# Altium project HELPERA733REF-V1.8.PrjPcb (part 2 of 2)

## Sheet 02 Power.SchDoc
size 386 x 246 mm
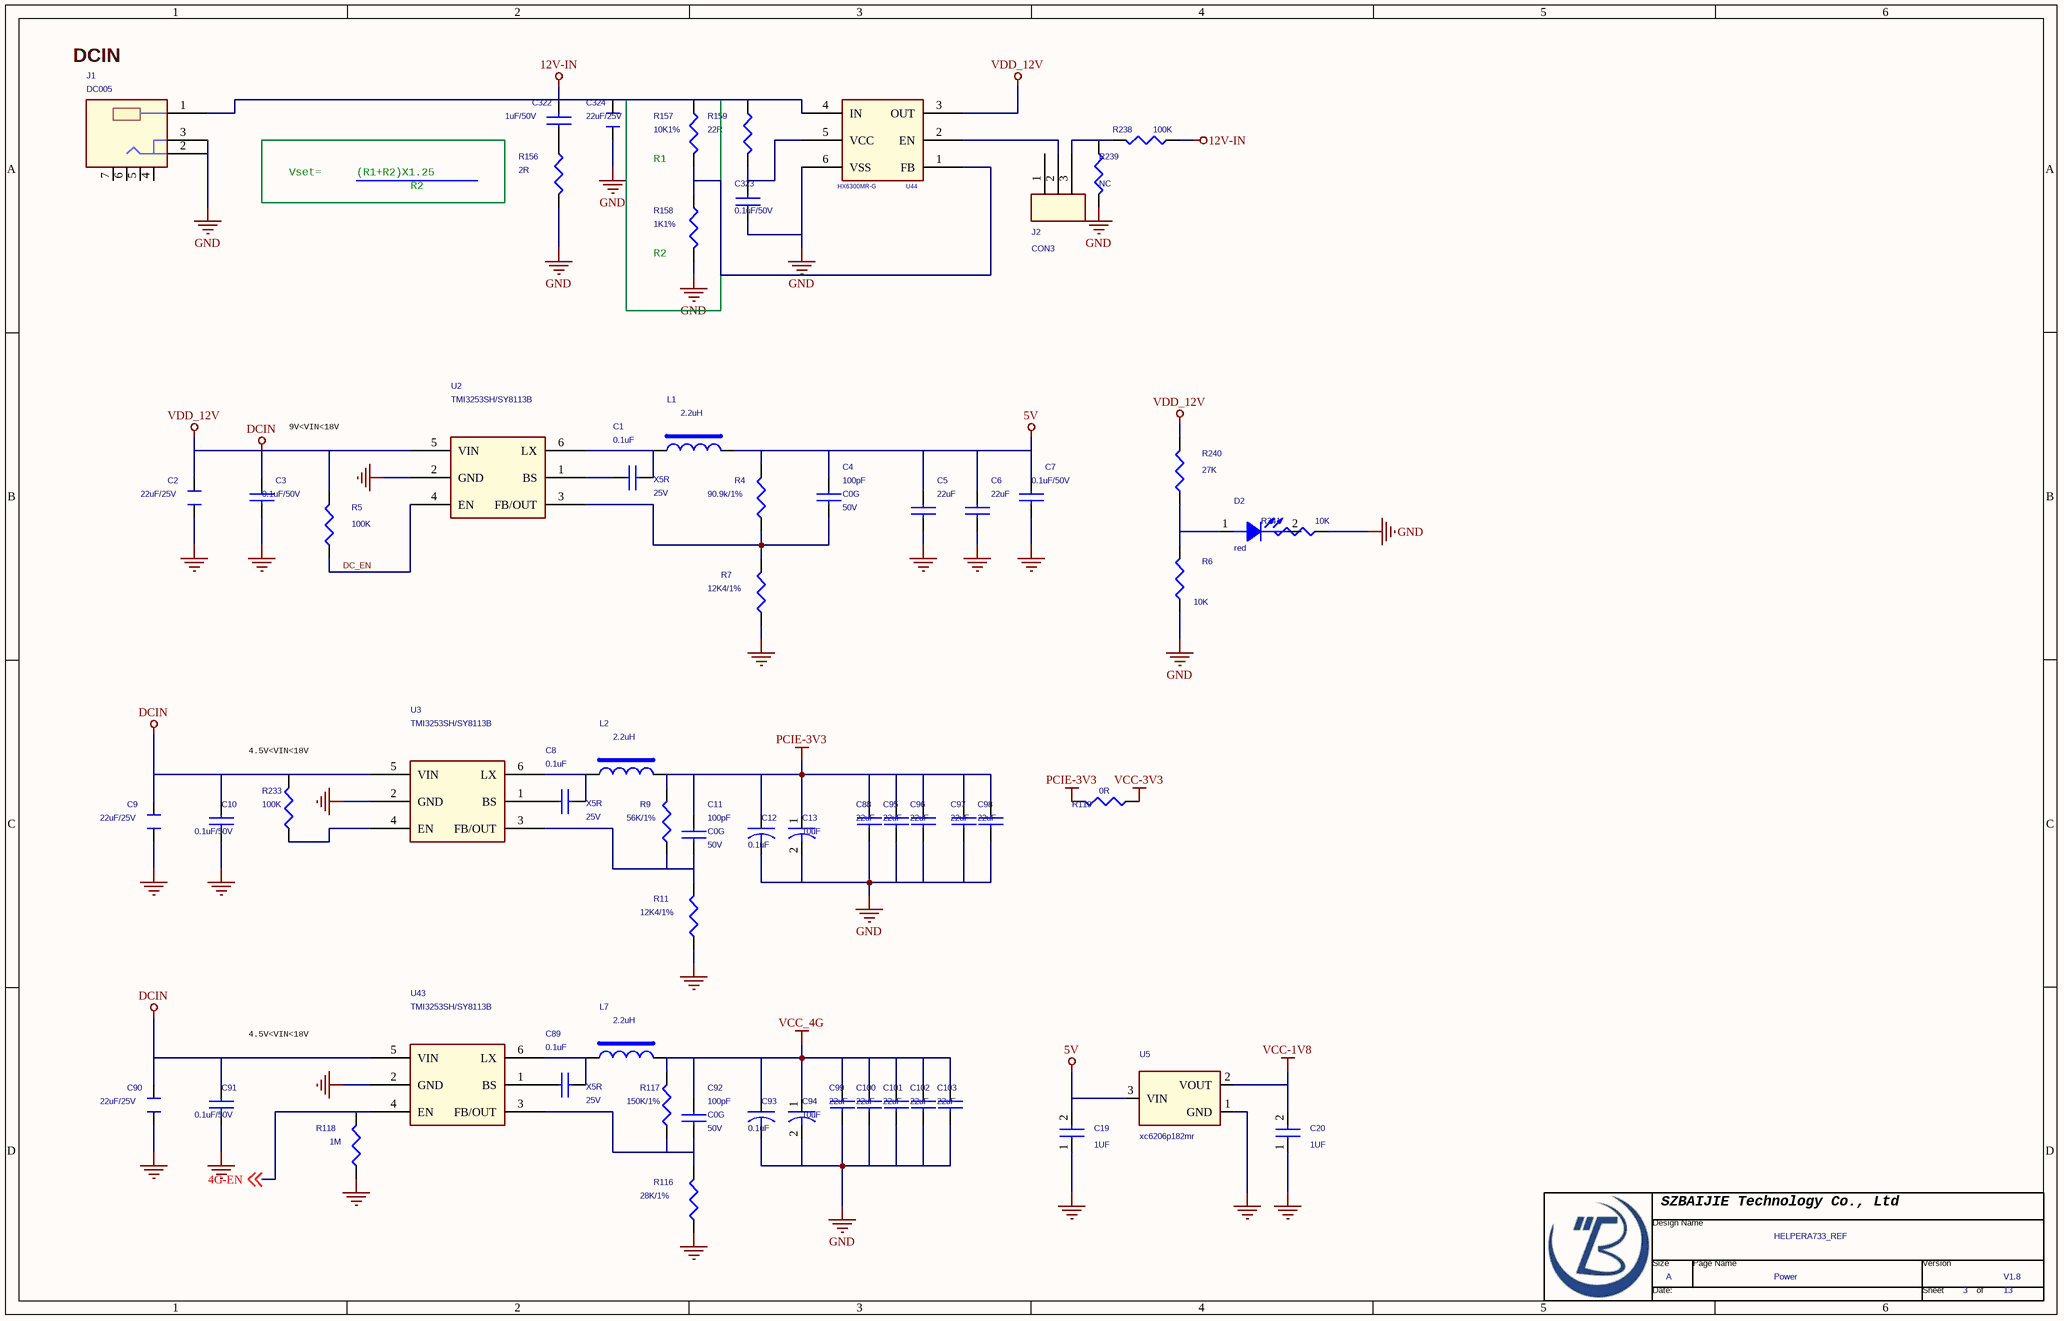
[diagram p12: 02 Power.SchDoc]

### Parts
(Parts that share a designator on the sheet are numbered #1, #2 ... from top to bottom, then left to right.)
*#11  Page Count: 13  Page Number: 3  Page Size: A  Title: HELPERA733_REF  RevCode: V1.8  Doc: Power  (hidden comment: TitleBlock0-BJ)  (graphical)
C1  0.1uF  Voltage: 25V  Dielectric: X5R  [C0402]
C2  22uF/25V  [C0805]
C3  0.1uF/50V  [C0402]
C4  100pF  Voltage: 50V  Dielectric: C0G  [C0402]
C5  22uF  [C0805]
C6  22uF  [C0805]
C7  0.1uF/50V  [C0402]
C8  0.1uF  Voltage: 25V  Dielectric: X5R  [C0402]
C9  22uF/25V  [C0805]
C10  0.1uF/50V  [C0402]
C11  100pF  Voltage: 50V  Dielectric: C0G  [C0402]
C12  0.1uF  [C0402]
C13  10uF  [C0603]
C19  1UF  [C0402]
C20  1UF  [C0402]
C88  22uF  [C0805]
C89  0.1uF  Voltage: 25V  Dielectric: X5R  [C0402]
C90  22uF/25V  [C0805]
C91  0.1uF/50V  [C0402]
C92  100pF  Voltage: 50V  Dielectric: C0G  [C0402]
C93  0.1uF  [C0402]
C94  10uF  [C0603]
C95  22uF  [C0805]
C96  22uF  [C0805]
C97  22uF  [C0805]
C98  22uF  [C0805]
C99  22uF  [C0805]
C100  22uF  [C0805]
C101  22uF  [C0805]
C102  22uF  [C0805]
C103  22uF  [C0805]
C322  1uF/50V  [C0603]
C323  0.1uF/50V  [C0402]
C324  22uF/25V  [C0805]
D2  red  [D0603]
J1  DC005  [TSH-3865D]
J2  CON3  [SS-12F44(1P2T)]
L1  2.2uH  [4018]
L2  2.2uH  [4018]
L7  2.2uH  [4018]
R4  90.9k/1%  [R0402]
R5  100K  [R0402]
R6  10K  [R0402]
R7  12K4/1%  [R0402]
R9  56K/1%  [R0402]
R11  12K4/1%  [R0402]
R116  28K/1%  [R0402]
R117  150K/1%  [R0402]
R118  1M  [R0402]
R119  0R  [R0805]
R156  2R  [R0603]
R157  10K1%  [R0402]
R158  1K1%  [R0402]
R159  22R  [R0402]
R233  100K  [R0402]
R238  100K  [R0402]
R239  NC  [R0402]
R240  27K  [R0402]
R241  10K  [R0402]
U2  TMI3253SH/SY8113B  [SOT23-6]
U3  TMI3253SH/SY8113B  [SOT23-6]
U5  xc6206p182mr  [SOT5P95B160_300H130]
U43  TMI3253SH/SY8113B  [SOT23-6]
U44  HX6300MR-G  [SOT89-5]

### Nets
5V: C4.1 C5.1 C6.1 C7.1 C19.2 L1.2 R4.1 U5.3(VIN)
12V-IN: C322.2 C324.1 J1.1 R157.1 R159.1 R238.2 U44.4(IN)
DCIN: C2.1 C3.1 C9.1 C10.1 C90.1 C91.1 R5.1 R233.1 R240.2 U2.5(VIN) U3.5(VIN) U43.5(VIN) U44.3(OUT)  [also labelled VDD_12V]
GND: C2.2 C3.2 C5.2 C6.2 C7.2 C9.2 C10.2 C12.2 C13.2 C19.1 C20.1 C88.2 C90.2 C91.2 C93.2 C94.2 C95.2 C96.2 C97.2 C98.2 C99.2 C100.2 C101.2 C102.2 C103.2 C323.1 C324.2 J1.2 J1.3 R6.1 R7.2 R11.2 R116.2 R118.2 R156.2 R158.2 R239.1 R241.1 U2.2(GND) U3.2(GND) U5.1(GND) U43.2(GND) U44.6(VSS)
PCIE-3V3: C11.1 C12.1 C13.1 C88.1 C95.1 C96.1 C97.1 C98.1 L2.2 R9.1 R119.2
VCC-1V8: C20.2 U5.2(VOUT)
VCC-3V3: R119.1
VCC_4G: C92.1 C93.1 C94.1 C99.1 C100.1 C101.1 C102.1 C103.1 L7.2 R117.1
4G-EN: R118.1 U43.4(EN) ; off-sheet 4G-EN
DC_EN: R5.2 U2.4(EN)
NetC1_1: C1.1 U2.1(BS)
NetC1_2: C1.2 L1.1 U2.6(LX)
NetC4_2: C4.2 R4.2 R7.1 U2.3(FB/OUT)
NetC8_1: C8.1 U3.1(BS)
NetC8_2: C8.2 L2.1 U3.6(LX)
NetC11_2: C11.2 R9.2 R11.1 U3.3(FB/OUT)
NetC89_1: C89.1 U43.1(BS)
NetC89_2: C89.2 L7.1 U43.6(LX)
NetC92_2: C92.2 R116.1 R117.2 U43.3(FB/OUT)
NetC322_1: C322.1 R156.1
NetC323_2: C323.2 R159.2 U44.5(VCC)
NetD2_1: D2.1(ANODE) R6.2 R240.1
NetD2_2: D2.2(CATHODE) R241.2
NetJ2_2: J2.2 U44.2(EN)
NetJ2_3: J2.3 R238.1 R239.2
NetR157_2: R157.2 R158.1 U44.1(FB)
NetR233_2: R233.2 U3.4(EN)

Not connected (* = marked no-connect by the designer): J1 4 5 6 7; J2 1

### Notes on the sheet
- (near J1) DCIN
- Vset=
- (R1+R2)X1.25
- R2
- (near R157) R1
- (near R158) R2
- 9V<VIN<18V
- (near R233) 4.5V<VIN<18V
- 4.5V<VIN<18V

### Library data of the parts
C1 C10 C91 = CAP NP_3: cap,100.00nF,+/-10%,25V,X5R,C0402; Tolerance: 10%; Priority: A
C2 C9 C90 C324 = CAPACITOR_0_Dup1
C3 C8 C89 = CAP NP_3: cap,100.00nF,+/-10%,25V,X5R,C0402; Priority: A; Tolerance: 10%
C4 C11 C92 C96-C98 C101 = CAP NP_3: cap,100.00pF,+/-5%,50V,C0G,C0402; Priority: A; Tolerance: 5%
C5 = CAP NP_3: cap,22.00uF,+/-10%,10V,X5R,C0805; Priority: A; Tolerance: 10%
C6 = CAP NP_3: cap,22.00uF,+/-10%,10V,X5R,C0805; Tolerance: 10%; Priority: A
C7 = CAP NP_3: cap,100.00nF,+/-10%,16V,X5R,C0402; Tolerance: 10%; Priority: A
C12 C93 = CAPACITOR
C13 C94 = CAPACITOR_0_Dup2
C19 C20 = CAP NP_0
C88 C95 C99 C100 C102 C103 = CAP NP_3: cap,100.00pF,+/-5%,50V,C0G,C0402; Tolerance: 5%; Priority: A
C322 C323 = CAP NP
D2 = LED_0
J1 = PHONOJACK_3: ￠3.5DC电源座　前插后贴　5PIN，两定位柱，高4.7mm; PART NUMBER: ZDC-BCT05-1000; Vendor: 质友; SPREADWIN PN: E10000040A
L1 L2 = ind1: Power Inductor,3.3uH,0.2,IND_404030; DC Resistor: 0.04ohm; Isat: 3.3A; Resonace frequency: 38M; Irms: 2.4A; Tolerance: 20%; Priority: A
L7 = ind1: Power Inductor,3.3uH,0.2,IND_404030; DC Resistor: 0.04ohm; Isat: 3.3A; Priority: A; Tolerance: 20%; Irms: 2.4A; Resonace frequency: 38M
R4 R5 R7 R9 R11 R116-R118 R233 R238 R239 = RESISTOR_1: RES,thick film,47KOhm,+/-5%,1/16W,SMD0402
R6 R119 R240 R241 = R_Dup6
R156-R159 = R
U2 U3 U43 = DCDC_SY8113: Priority: A
U5 = SGM2028_0: ID: U-IC0031; Parameter: SOT23-5,input 2.5~5.5V,current=0.5A
U44 = PT4110_0

## Sheet 01 CORE.SchDoc
size 513 x 386 mm
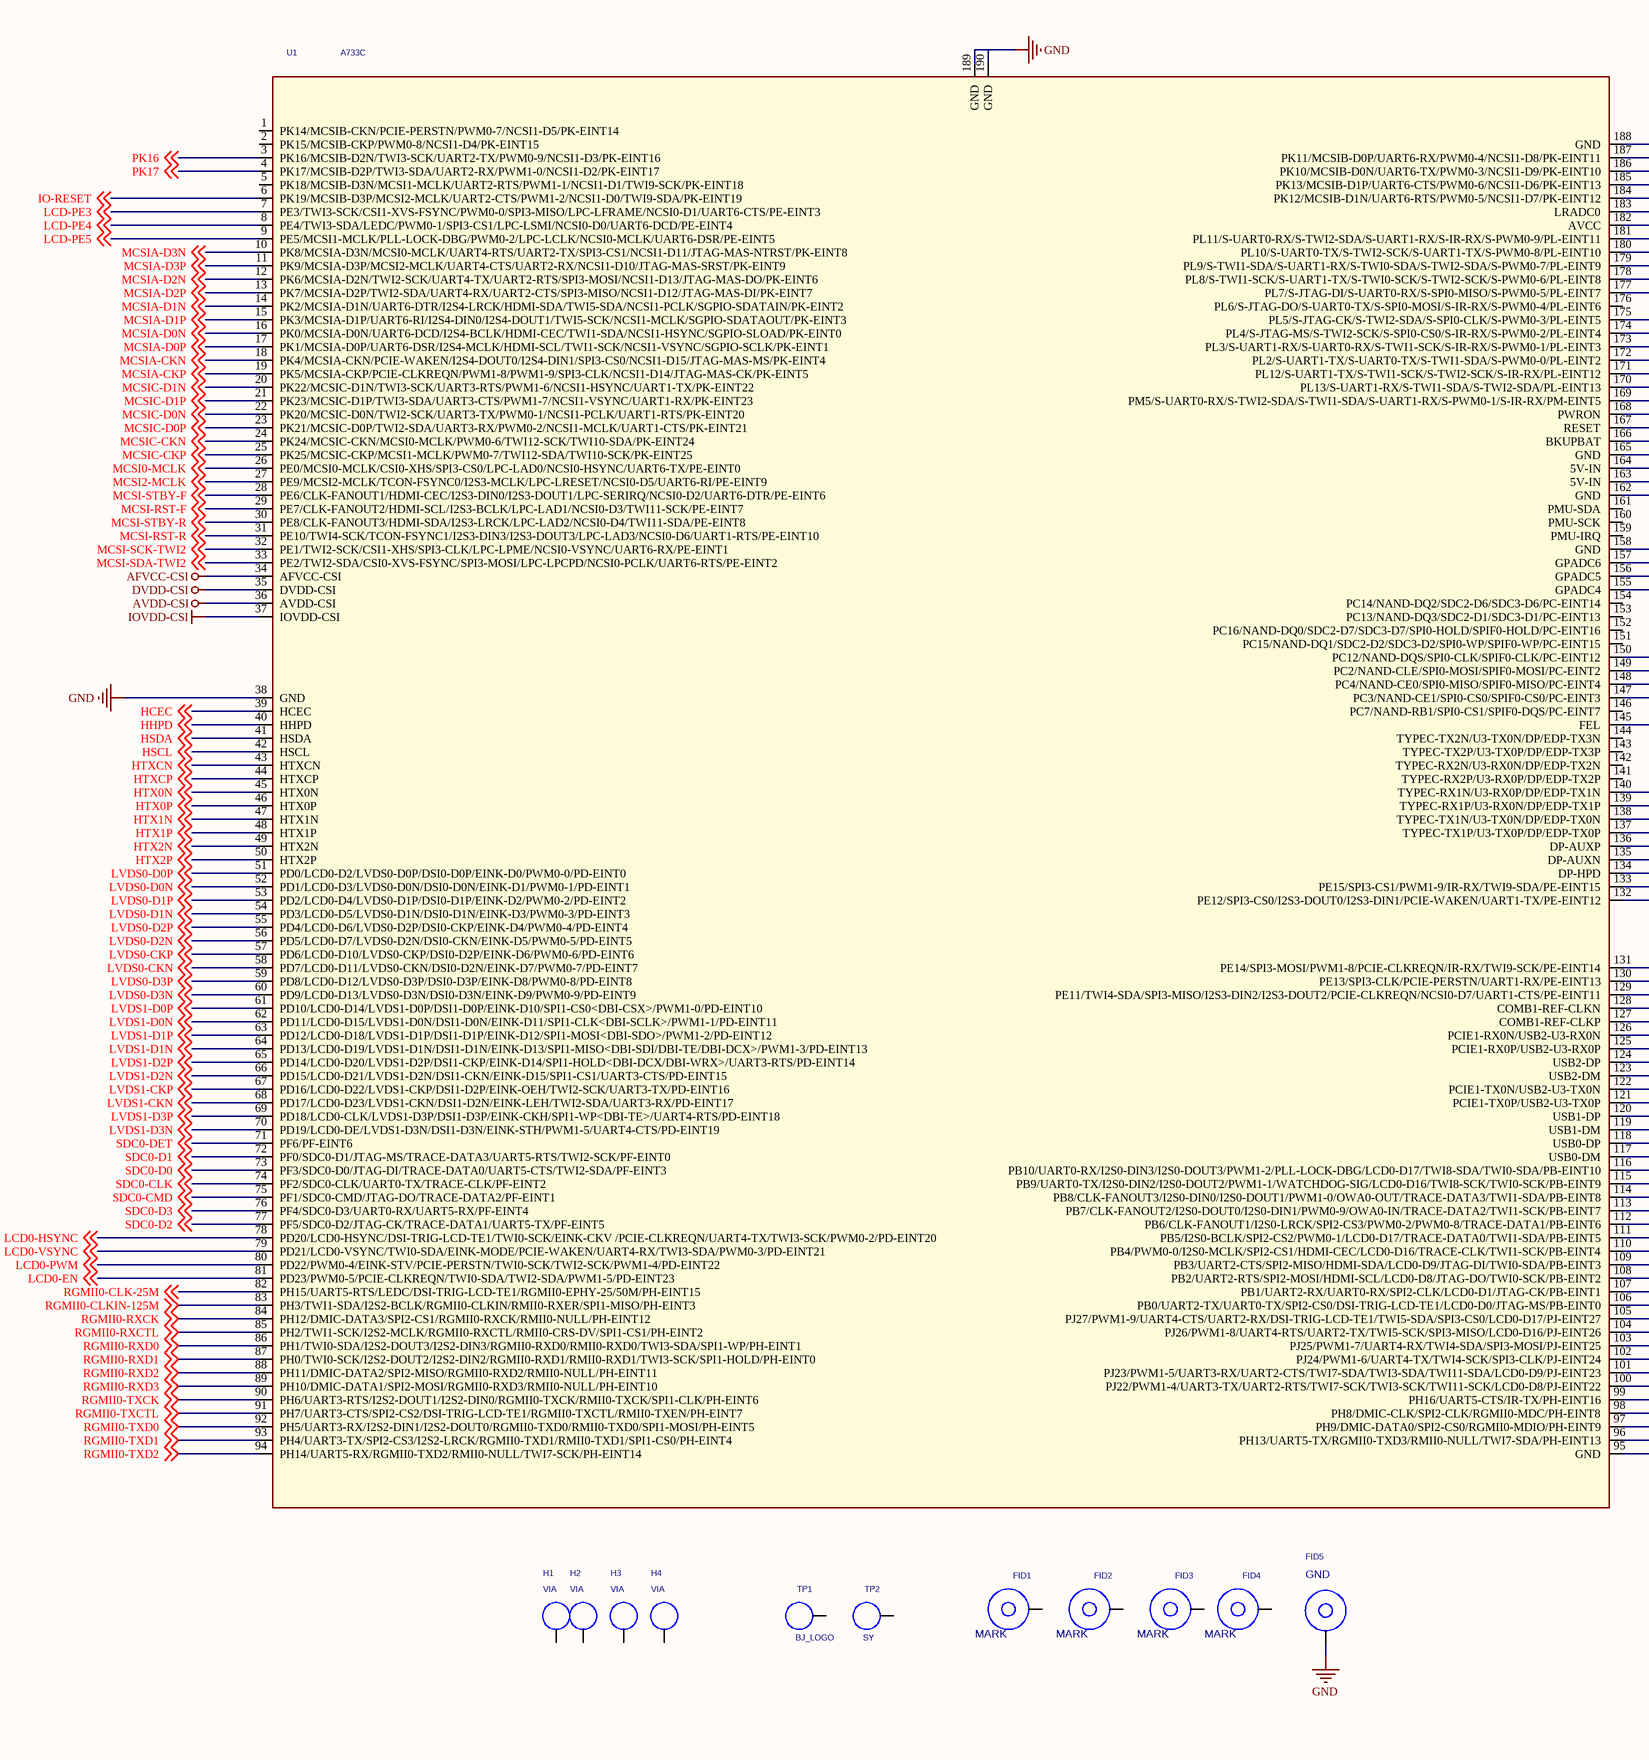
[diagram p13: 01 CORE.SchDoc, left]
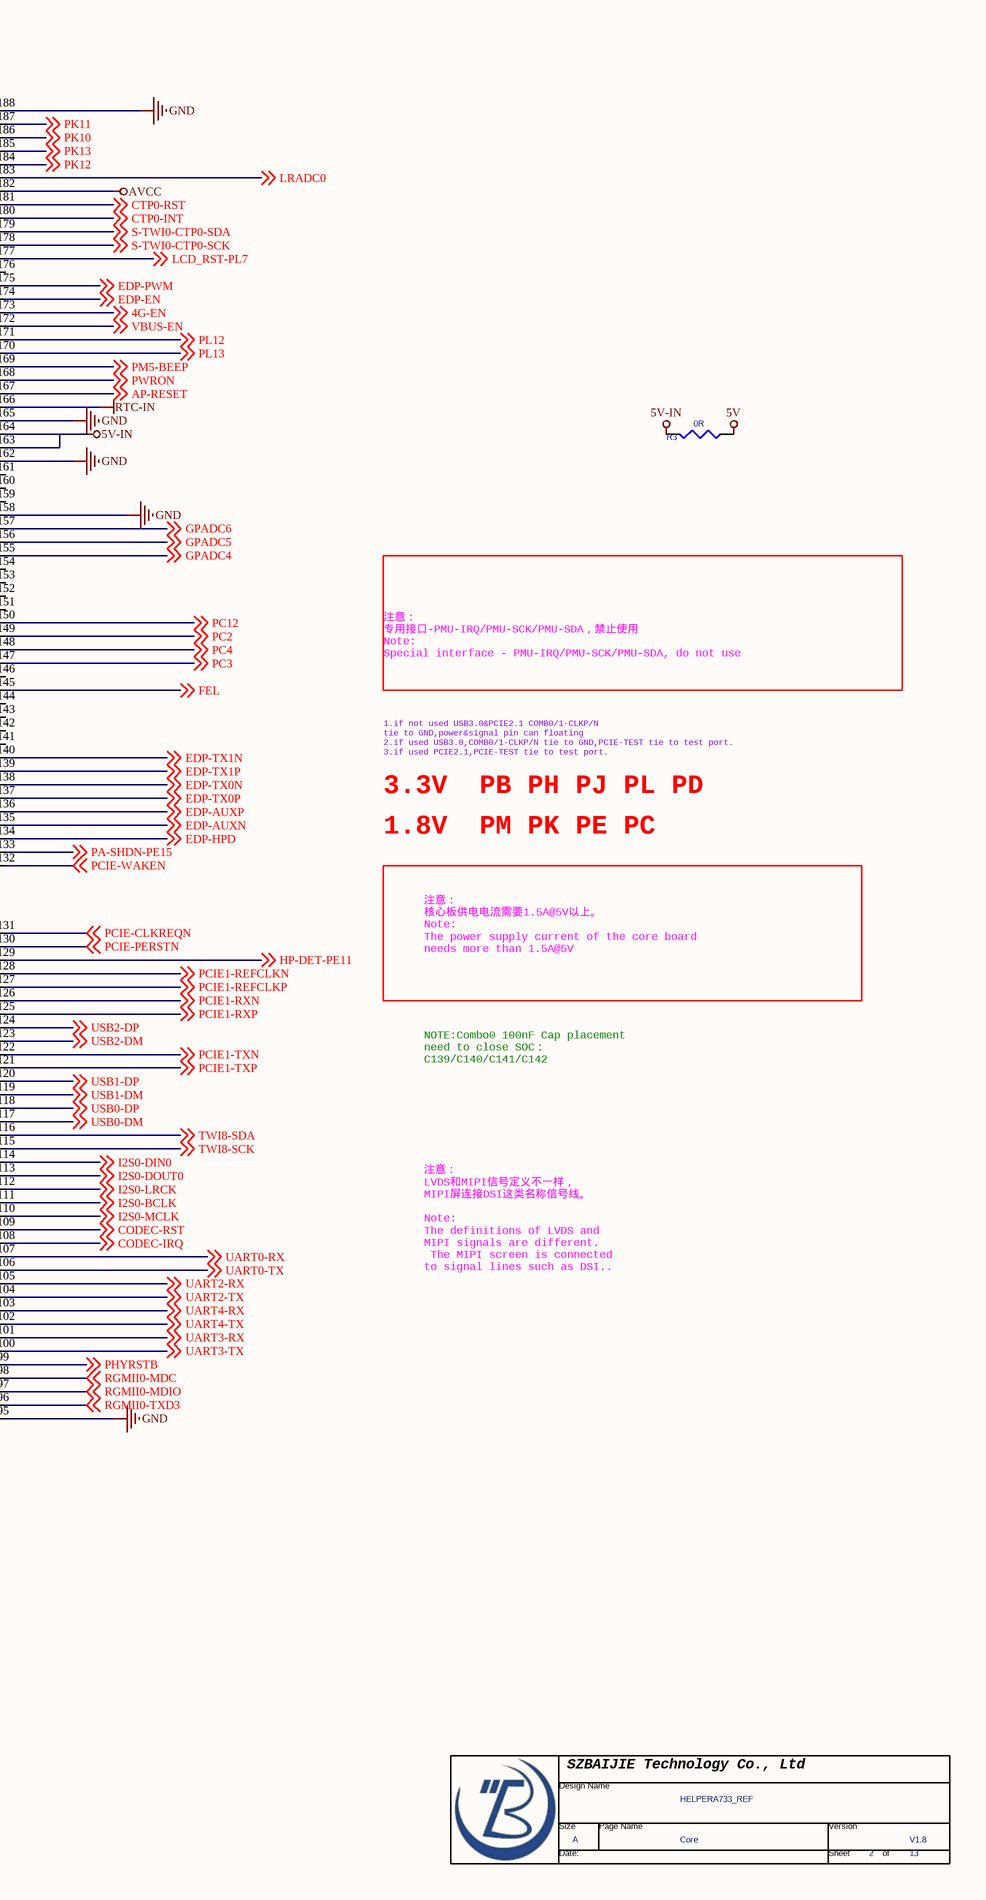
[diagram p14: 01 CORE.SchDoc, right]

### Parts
(Parts that share a designator on the sheet are numbered #1, #2 ... from top to bottom, then left to right.)
*#12  Page Count: 13  Page Number: 2  Page Size: A  Title: HELPERA733_REF  RevCode: V1.8  Doc: Core  (hidden comment: TitleBlock0-BJ)  (graphical)
FID1  MARK  [FIDICALMARK]
FID2  MARK  [FIDICALMARK]
FID3  MARK  [FIDICALMARK]
FID4  MARK  [FIDICALMARK]
FID5  GND  [FIDICALMARK]
H1  VIA  [DV]
H2  VIA  [DV]
H3  VIA  [DV]
H4  VIA  [DV]
R3  0R  [R0805]
TP1  BJ_LOGO  [BJ_LOGO]
TP2  SY  [6X6]
U1  A733C  [HELPERA733D-2]

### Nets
5V: R3.1
5V-IN: R3.2 U1.163(5V-IN) U1.164(5V-IN)
AFVCC-CSI: U1.34(AFVCC-CSI)
AVCC: U1.182(AVCC)
AVDD-CSI: U1.36(AVDD-CSI)
DVDD-CSI: U1.35(DVDD-CSI)
GND: FID5.1(TP) U1.38(GND) U1.95(GND) U1.158(GND) U1.162(GND) U1.165(GND) U1.188(GND) U1.189(GND) U1.190(GND)
IOVDD-CSI: U1.37(IOVDD-CSI)
RTC-IN: U1.166(BKUPBAT)
4G-EN: U1.173(PL3/S-UART1-RX/S-UART0-RX/S-TWI1-SCK/S-IR-RX/S-PWM0-1/PL-EINT3) ; off-sheet 4G-EN
AP-RESET: U1.167(RESET) ; off-sheet AP-RESET
CODEC-IRQ: U1.108(PB2/UART2-RTS/SPI2-MOSI/HDMI-SCL/LCD0-D8/JTAG-DO/TWI0-SCK/PB-EINT2) ; off-sheet CODEC-IRQ
CODEC-RST: U1.109(PB3/UART2-CTS/SPI2-MISO/HDMI-SDA/LCD0-D9/JTAG-DI/TWI0-SDA/PB-EINT3) ; off-sheet CODEC-RST
CTP0-INT: U1.180(PL10/S-UART0-TX/S-TWI2-SCK/S-UART1-TX/S-PWM0-8/PL-EINT10) ; off-sheet CTP0-INT
CTP0-RST: U1.181(PL11/S-UART0-RX/S-TWI2-SDA/S-UART1-RX/S-IR-RX/S-PWM0-9/PL-EINT11) ; off-sheet CTP0-RST
EDP-AUXN: U1.135(DP-AUXN) ; off-sheet EDP-AUXN
EDP-AUXP: U1.136(DP-AUXP) ; off-sheet EDP-AUXP
EDP-EN: U1.174(PL4/S-JTAG-MS/S-TWI2-SCK/S-SPI0-CS0/S-IR-RX/S-PWM0-2/PL-EINT4) ; off-sheet EDP-EN
EDP-HPD: U1.134(DP-HPD) ; off-sheet EDP-HPD
EDP-PWM: U1.175(PL5/S-JTAG-CK/S-TWI2-SDA/S-SPI0-CLK/S-PWM0-3/PL-EINT5) ; off-sheet EDP-PWM  [project net EDP-BL-PWMI]
EDP-TX0N: U1.138(TYPEC-TX1N/U3-TX0N/DP/EDP-TX0N) ; off-sheet EDP-TX0N
EDP-TX0P: U1.137(TYPEC-TX1P/U3-TX0P/DP/EDP-TX0P) ; off-sheet EDP-TX0P
EDP-TX1N: U1.140(TYPEC-RX1N/U3-RX0P/DP/EDP-TX1N) ; off-sheet EDP-TX1N
EDP-TX1P: U1.139(TYPEC-RX1P/U3-RX0N/DP/EDP-TX1P) ; off-sheet EDP-TX1P
FEL: U1.145(FEL) ; off-sheet FEL
GPADC4: U1.155(GPADC4) ; off-sheet GPADC4
GPADC5: U1.156(GPADC5) ; off-sheet GPADC5
GPADC6: U1.157(GPADC6) ; off-sheet GPADC6
HCEC: U1.39(HCEC) ; off-sheet HCEC
HHPD: U1.40(HHPD) ; off-sheet HHPD
HP-DET-PE11: U1.129(PE11/TWI4-SDA/SPI3-MISO/I2S3-DIN2/I2S3-DOUT2/PCIE-CLKREQN/NCSI0-D7/UART1-CTS/PE-EINT11) ; off-sheet HP-DET-PE11
HSCL: U1.42(HSCL) ; off-sheet HSCL
HSDA: U1.41(HSDA) ; off-sheet HSDA
HTX0N: U1.45(HTX0N) ; off-sheet HTX0N
HTX0P: U1.46(HTX0P) ; off-sheet HTX0P
HTX1N: U1.47(HTX1N) ; off-sheet HTX1N
HTX1P: U1.48(HTX1P) ; off-sheet HTX1P
HTX2N: U1.49(HTX2N) ; off-sheet HTX2N
HTX2P: U1.50(HTX2P) ; off-sheet HTX2P
HTXCN: U1.43(HTXCN) ; off-sheet HTXCN
HTXCP: U1.44(HTXCP) ; off-sheet HTXCP
I2S0-BCLK: U1.111(PB5/I2S0-BCLK/SPI2-CS2/PWM0-1/LCD0-D17/TRACE-DATA0/TWI1-SDA/PB-EINT5) ; off-sheet I2S0-BCLK  [project net AUDIO-BCLK]
I2S0-DIN0: U1.114(PB8/CLK-FANOUT3/I2S0-DIN0/I2S0-DOUT1/PWM1-0/OWA0-OUT/TRACE-DATA3/TWI1-SDA/PB-EINT8) ; off-sheet I2S0-DIN0  [project net AUDIO-DIN]
I2S0-DOUT0: U1.113(PB7/CLK-FANOUT2/I2S0-DOUT0/I2S0-DIN1/PWM0-9/OWA0-IN/TRACE-DATA2/TWI1-SCK/PB-EINT7) ; off-sheet I2S0-DOUT0  [project net AUDIO-DOUT]
I2S0-LRCK: U1.112(PB6/CLK-FANOUT1/I2S0-LRCK/SPI2-CS3/PWM0-2/PWM0-8/TRACE-DATA1/PB-EINT6) ; off-sheet I2S0-LRCK  [project net AUDIO-LRCK]
I2S0-MCLK: U1.110(PB4/PWM0-0/I2S0-MCLK/SPI2-CS1/HDMI-CEC/LCD0-D16/TRACE-CLK/TWI1-SCK/PB-EINT4) ; off-sheet I2S0-MCLK  [project net AUDIO-MCLK]
IO-RESET: U1.6(PK19/MCSIB-D3P/MCSI2-MCLK/UART2-CTS/PWM1-2/NCSI1-D0/TWI9-SDA/PK-EINT19) ; off-sheet IO-RESET
LCD0-EN: U1.81(PD23/PWM0-5/PCIE-CLKREQN/TWI0-SDA/TWI2-SDA/PWM1-5/PD-EINT23) ; off-sheet LCD0-EN
LCD0-HSYNC: U1.78(PD20/LCD0-HSYNC/DSI-TRIG-LCD-TE1/TWI0-SCK/EINK-CKV_/PCIE-CLKREQN/UART4-TX/TWI3-SCK/PWM0-2/PD-EINT20) ; off-sheet LCD0-HSYNC
LCD0-PWM: U1.80(PD22/PWM0-4/EINK-STV/PCIE-PERSTN/TWI0-SCK/TWI2-SCK/PWM1-4/PD-EINT22) ; off-sheet LCD0-PWM
LCD0-VSYNC: U1.79(PD21/LCD0-VSYNC/TWI0-SDA/EINK-MODE/PCIE-WAKEN/UART4-RX/TWI3-SDA/PWM0-3/PD-EINT21) ; off-sheet LCD0-VSYNC
LCD-PE3: U1.7(PE3/TWI3-SCK/CSI1-XVS-FSYNC/PWM0-0/SPI3-MISO/LPC-LFRAME/NCSI0-D1/UART6-CTS/PE-EINT3) ; off-sheet LCD-PE3
LCD-PE4: U1.8(PE4/TWI3-SDA/LEDC/PWM0-1/SPI3-CS1/LPC-LSMI/NCSI0-D0/UART6-DCD/PE-EINT4) ; off-sheet LCD-PE4
LCD-PE5: U1.9(PE5/MCSI1-MCLK/PLL-LOCK-DBG/PWM0-2/LPC-LCLK/NCSI0-MCLK/UART6-DSR/PE-EINT5) ; off-sheet LCD-PE5
LCD_RST-PL7: U1.177(PL7/S-JTAG-DI/S-UART0-RX/S-SPI0-MISO/S-PWM0-5/PL-EINT7) ; off-sheet LCD_RST-PL7  [project net LCD-RST]
LRADC0: U1.183(LRADC0) ; off-sheet LRADC0
LVDS0-CKN: U1.58(PD7/LCD0-D11/LVDS0-CKN/DSI0-D2N/EINK-D7/PWM0-7/PD-EINT7) ; off-sheet LVDS0-CKN  [project net DSI0-DN2]
LVDS0-CKP: U1.57(PD6/LCD0-D10/LVDS0-CKP/DSI0-D2P/EINK-D6/PWM0-6/PD-EINT6) ; off-sheet LVDS0-CKP  [project net DSI0-DP2]
LVDS0-D0N: U1.52(PD1/LCD0-D3/LVDS0-D0N/DSI0-D0N/EINK-D1/PWM0-1/PD-EINT1) ; off-sheet LVDS0-D0N  [project net DSI0-DN0]
LVDS0-D0P: U1.51(PD0/LCD0-D2/LVDS0-D0P/DSI0-D0P/EINK-D0/PWM0-0/PD-EINT0) ; off-sheet LVDS0-D0P  [project net DSI0-DP0]
LVDS0-D1N: U1.54(PD3/LCD0-D5/LVDS0-D1N/DSI0-D1N/EINK-D3/PWM0-3/PD-EINT3) ; off-sheet LVDS0-D1N  [project net DSI0-DN1]
LVDS0-D1P: U1.53(PD2/LCD0-D4/LVDS0-D1P/DSI0-D1P/EINK-D2/PWM0-2/PD-EINT2) ; off-sheet LVDS0-D1P  [project net DSI0-DP1]
LVDS0-D2N: U1.56(PD5/LCD0-D7/LVDS0-D2N/DSI0-CKN/EINK-D5/PWM0-5/PD-EINT5) ; off-sheet LVDS0-D2N  [project net DSI0-CKN]
LVDS0-D2P: U1.55(PD4/LCD0-D6/LVDS0-D2P/DSI0-CKP/EINK-D4/PWM0-4/PD-EINT4) ; off-sheet LVDS0-D2P  [project net DSI0-CKP]
LVDS0-D3N: U1.60(PD9/LCD0-D13/LVDS0-D3N/DSI0-D3N/EINK-D9/PWM0-9/PD-EINT9) ; off-sheet LVDS0-D3N  [project net DSI0-DN3]
LVDS0-D3P: U1.59(PD8/LCD0-D12/LVDS0-D3P/DSI0-D3P/EINK-D8/PWM0-8/PD-EINT8) ; off-sheet LVDS0-D3P  [project net DSI0-DP3]
LVDS1-CKN: U1.68(PD17/LCD0-D23/LVDS1-CKN/DSI1-D2N/EINK-LEH/TWI2-SDA/UART3-RX/PD-EINT17) ; off-sheet LVDS1-CKN  [project net DSI1-DN2]
LVDS1-CKP: U1.67(PD16/LCD0-D22/LVDS1-CKP/DSI1-D2P/EINK-OEH/TWI2-SCK/UART3-TX/PD-EINT16) ; off-sheet LVDS1-CKP  [project net DSI1-DP2]
LVDS1-D0N: U1.62(PD11/LCD0-D15/LVDS1-D0N/DSI1-D0N/EINK-D11/SPI1-CLK<DBI-SCLK>/PWM1-1/PD-EINT11) ; off-sheet LVDS1-D0N  [project net DSI1-DN0]
LVDS1-D0P: U1.61(PD10/LCD0-D14/LVDS1-D0P/DSI1-D0P/EINK-D10/SPI1-CS0<DBI-CSX>/PWM1-0/PD-EINT10) ; off-sheet LVDS1-D0P  [project net DSI1-DP0]
LVDS1-D1N: U1.64(PD13/LCD0-D19/LVDS1-D1N/DSI1-D1N/EINK-D13/SPI1-MISO<DBI-SDI/DBI-TE/DBI-DCX>/PWM1-3/PD-EINT13) ; off-sheet LVDS1-D1N  [project net DSI1-DN1]
LVDS1-D1P: U1.63(PD12/LCD0-D18/LVDS1-D1P/DSI1-D1P/EINK-D12/SPI1-MOSI<DBI-SDO>/PWM1-2/PD-EINT12) ; off-sheet LVDS1-D1P  [project net DSI1-DP1]
LVDS1-D2N: U1.66(PD15/LCD0-D21/LVDS1-D2N/DSI1-CKN/EINK-D15/SPI1-CS1/UART3-CTS/PD-EINT15) ; off-sheet LVDS1-D2N  [project net DSI1-CKN]
LVDS1-D2P: U1.65(PD14/LCD0-D20/LVDS1-D2P/DSI1-CKP/EINK-D14/SPI1-HOLD<DBI-DCX/DBI-WRX>/UART3-RTS/PD-EINT14) ; off-sheet LVDS1-D2P  [project net DSI1-CKP]
LVDS1-D3N: U1.70(PD19/LCD0-DE/LVDS1-D3N/DSI1-D3N/EINK-STH/PWM1-5/UART4-CTS/PD-EINT19) ; off-sheet LVDS1-D3N  [project net DSI1-DN3]
LVDS1-D3P: U1.69(PD18/LCD0-CLK/LVDS1-D3P/DSI1-D3P/EINK-CKH/SPI1-WP<DBI-TE>/UART4-RTS/PD-EINT18) ; off-sheet LVDS1-D3P  [project net DSI1-DP3]
MCSI0-MCLK: U1.26(PE0/MCSI0-MCLK/CSI0-XHS/SPI3-CS0/LPC-LAD0/NCSI0-HSYNC/UART6-TX/PE-EINT0) ; off-sheet MCSI0-MCLK
MCSI2-MCLK: U1.27(PE9/MCSI2-MCLK/TCON-FSYNC0/I2S3-MCLK/LPC-LRESET/NCSI0-D5/UART6-RI/PE-EINT9) ; off-sheet MCSI2-MCLK
MCSI-RST-F: U1.29(PE7/CLK-FANOUT2/HDMI-SCL/I2S3-BCLK/LPC-LAD1/NCSI0-D3/TWI11-SCK/PE-EINT7) ; off-sheet MCSI-RST-F
MCSI-RST-R: U1.31(PE10/TWI4-SCK/TCON-FSYNC1/I2S3-DIN3/I2S3-DOUT3/LPC-LAD3/NCSI0-D6/UART1-RTS/PE-EINT10) ; off-sheet MCSI-RST-R
MCSI-SCK-TWI2: U1.32(PE1/TWI2-SCK/CSI1-XHS/SPI3-CLK/LPC-LPME/NCSI0-VSYNC/UART6-RX/PE-EINT1) ; off-sheet MCSI-SCK-TWI2
MCSI-SDA-TWI2: U1.33(PE2/TWI2-SDA/CSI0-XVS-FSYNC/SPI3-MOSI/LPC-LPCPD/NCSI0-PCLK/UART6-RTS/PE-EINT2) ; off-sheet MCSI-SDA-TWI2
MCSI-STBY-F: U1.28(PE6/CLK-FANOUT1/HDMI-CEC/I2S3-DIN0/I2S3-DOUT1/LPC-SERIRQ/NCSI0-D2/UART6-DTR/PE-EINT6) ; off-sheet MCSI-STBY-F
MCSI-STBY-R: U1.30(PE8/CLK-FANOUT3/HDMI-SDA/I2S3-LRCK/LPC-LAD2/NCSI0-D4/TWI11-SDA/PE-EINT8) ; off-sheet MCSI-STBY-R
MCSIA-CKN: U1.18(PK4/MCSIA-CKN/PCIE-WAKEN/I2S4-DOUT0/I2S4-DIN1/SPI3-CS0/NCSI1-D15/JTAG-MAS-MS/PK-EINT4) ; off-sheet MCSIA-CKN
MCSIA-CKP: U1.19(PK5/MCSIA-CKP/PCIE-CLKREQN/PWM1-8/PWM1-9/SPI3-CLK/NCSI1-D14/JTAG-MAS-CK/PK-EINT5) ; off-sheet MCSIA-CKP
MCSIA-D0N: U1.16(PK0/MCSIA-D0N/UART6-DCD/I2S4-BCLK/HDMI-CEC/TWI1-SDA/NCSI1-HSYNC/SGPIO-SLOAD/PK-EINT0) ; off-sheet MCSIA-D0N
MCSIA-D0P: U1.17(PK1/MCSIA-D0P/UART6-DSR/I2S4-MCLK/HDMI-SCL/TWI1-SCK/NCSI1-VSYNC/SGPIO-SCLK/PK-EINT1) ; off-sheet MCSIA-D0P
MCSIA-D1N: U1.14(PK2/MCSIA-D1N/UART6-DTR/I2S4-LRCK/HDMI-SDA/TWI5-SDA/NCSI1-PCLK/SGPIO-SDATAIN/PK-EINT2) ; off-sheet MCSIA-D1N
MCSIA-D1P: U1.15(PK3/MCSIA-D1P/UART6-RI/I2S4-DIN0/I2S4-DOUT1/TWI5-SCK/NCSI1-MCLK/SGPIO-SDATAOUT/PK-EINT3) ; off-sheet MCSIA-D1P
MCSIA-D2N: U1.12(PK6/MCSIA-D2N/TWI2-SCK/UART4-TX/UART2-RTS/SPI3-MOSI/NCSI1-D13/JTAG-MAS-DO/PK-EINT6) ; off-sheet MCSIA-D2N
MCSIA-D2P: U1.13(PK7/MCSIA-D2P/TWI2-SDA/UART4-RX/UART2-CTS/SPI3-MISO/NCSI1-D12/JTAG-MAS-DI/PK-EINT7) ; off-sheet MCSIA-D2P
MCSIA-D3N: U1.10(PK8/MCSIA-D3N/MCSI0-MCLK/UART4-RTS/UART2-TX/SPI3-CS1/NCSI1-D11/JTAG-MAS-NTRST/PK-EINT8) ; off-sheet MCSIA-D3N
MCSIA-D3P: U1.11(PK9/MCSIA-D3P/MCSI2-MCLK/UART4-CTS/UART2-RX/NCSI1-D10/JTAG-MAS-SRST/PK-EINT9) ; off-sheet MCSIA-D3P
MCSIC-CKN: U1.24(PK24/MCSIC-CKN/MCSI0-MCLK/PWM0-6/TWI12-SCK/TWI10-SDA/PK-EINT24) ; off-sheet MCSIC-CKN
MCSIC-CKP: U1.25(PK25/MCSIC-CKP/MCSI1-MCLK/PWM0-7/TWI12-SDA/TWI10-SCK/PK-EINT25) ; off-sheet MCSIC-CKP
MCSIC-D0N: U1.22(PK20/MCSIC-D0N/TWI2-SCK/UART3-TX/PWM0-1/NCSI1-PCLK/UART1-RTS/PK-EINT20) ; off-sheet MCSIC-D0N
MCSIC-D0P: U1.23(PK21/MCSIC-D0P/TWI2-SDA/UART3-RX/PWM0-2/NCSI1-MCLK/UART1-CTS/PK-EINT21) ; off-sheet MCSIC-D0P
MCSIC-D1N: U1.20(PK22/MCSIC-D1N/TWI3-SCK/UART3-RTS/PWM1-6/NCSI1-HSYNC/UART1-TX/PK-EINT22) ; off-sheet MCSIC-D1N
MCSIC-D1P: U1.21(PK23/MCSIC-D1P/TWI3-SDA/UART3-CTS/PWM1-7/NCSI1-VSYNC/UART1-RX/PK-EINT23) ; off-sheet MCSIC-D1P
PA-SHDN-PE15: U1.133(PE15/SPI3-CS1/PWM1-9/IR-RX/TWI9-SDA/PE-EINT15) ; off-sheet PA-SHDN-PE15
PC2: U1.149(PC2/NAND-CLE/SPI0-MOSI/SPIF0-MOSI/PC-EINT2) ; off-sheet PC2
PC3: U1.147(PC3/NAND-CE1/SPI0-CS0/SPIF0-CS0/PC-EINT3) ; off-sheet PC3
PC4: U1.148(PC4/NAND-CE0/SPI0-MISO/SPIF0-MISO/PC-EINT4) ; off-sheet PC4
PC12: U1.150(PC12/NAND-DQS/SPI0-CLK/SPIF0-CLK/PC-EINT12) ; off-sheet PC12
PCIE1-REFCLKN: U1.128(COMB1-REF-CLKN) ; off-sheet PCIE1-REFCLKN
PCIE1-REFCLKP: U1.127(COMB1-REF-CLKP) ; off-sheet PCIE1-REFCLKP
PCIE1-RXN: U1.126(PCIE1-RX0N/USB2-U3-RX0N) ; off-sheet PCIE1-RXN
PCIE1-RXP: U1.125(PCIE1-RX0P/USB2-U3-RX0P) ; off-sheet PCIE1-RXP
PCIE1-TXN: U1.122(PCIE1-TX0N/USB2-U3-TX0N) ; off-sheet PCIE1-TXN
PCIE1-TXP: U1.121(PCIE1-TX0P/USB2-U3-TX0P) ; off-sheet PCIE1-TXP
PCIE-CLKREQN: U1.131(PE14/SPI3-MOSI/PWM1-8/PCIE-CLKREQN/IR-RX/TWI9-SCK/PE-EINT14) ; off-sheet PCIE-CLKREQN
PCIE-PERSTN: U1.130(PE13/SPI3-CLK/PCIE-PERSTN/UART1-RX/PE-EINT13) ; off-sheet PCIE-PERSTN
PCIE-WAKEN: U1.132(PE12/SPI3-CS0/I2S3-DOUT0/I2S3-DIN1/PCIE-WAKEN/UART1-TX/PE-EINT12) ; off-sheet PCIE-WAKEN
PHYRSTB: U1.99(PH16/UART5-CTS/IR-TX/PH-EINT16) ; off-sheet PHYRSTB
PK10: U1.186(PK10/MCSIB-D0N/UART6-TX/PWM0-3/NCSI1-D9/PK-EINT10) ; off-sheet PK10
PK11: U1.187(PK11/MCSIB-D0P/UART6-RX/PWM0-4/NCSI1-D8/PK-EINT11) ; off-sheet PK11
PK12: U1.184(PK12/MCSIB-D1N/UART6-RTS/PWM0-5/NCSI1-D7/PK-EINT12) ; off-sheet PK12
PK13: U1.185(PK13/MCSIB-D1P/UART6-CTS/PWM0-6/NCSI1-D6/PK-EINT13) ; off-sheet PK13
PK16: U1.3(PK16/MCSIB-D2N/TWI3-SCK/UART2-TX/PWM0-9/NCSI1-D3/PK-EINT16) ; off-sheet PK16
PK17: U1.4(PK17/MCSIB-D2P/TWI3-SDA/UART2-RX/PWM1-0/NCSI1-D2/PK-EINT17) ; off-sheet PK17
PL12: U1.171(PL12/S-UART1-TX/S-TWI1-SCK/S-TWI2-SCK/S-IR-RX/PL-EINT12) ; off-sheet PL12
PL13: U1.170(PL13/S-UART1-RX/S-TWI1-SDA/S-TWI2-SDA/PL-EINT13) ; off-sheet PL13
PM5-BEEP: U1.169(PM5/S-UART0-RX/S-TWI2-SDA/S-TWI1-SDA/S-UART1-RX/S-PWM0-1/S-IR-RX/PM-EINT5) ; off-sheet PM5-BEEP
PWRON: U1.168(PWRON) ; off-sheet PWRON
RGMII0-CLK-25M: U1.82(PH15/UART5-RTS/LEDC/DSI-TRIG-LCD-TE1/RGMII0-EPHY-25/50M/PH-EINT15) ; off-sheet RGMII0-CLK-25M
RGMII0-CLKIN-125M: U1.83(PH3/TWI1-SDA/I2S2-BCLK/RGMII0-CLKIN/RMII0-RXER/SPI1-MISO/PH-EINT3) ; off-sheet RGMII0-CLKIN-125M  [project net RGMII-CLKIN-125M]
RGMII0-MDC: U1.98(PH8/DMIC-CLK/SPI2-CLK/RGMII0-MDC/PH-EINT8) ; off-sheet RGMII0-MDC  [project net MDC]
RGMII0-MDIO: U1.97(PH9/DMIC-DATA0/SPI2-CS0/RGMII0-MDIO/PH-EINT9) ; off-sheet RGMII0-MDIO  [project net MDIO]
RGMII0-RXCK: U1.84(PH12/DMIC-DATA3/SPI2-CS1/RGMII0-RXCK/RMII0-NULL/PH-EINT12) ; off-sheet RGMII0-RXCK
RGMII0-RXCTL: U1.85(PH2/TWI1-SCK/I2S2-MCLK/RGMII0-RXCTL/RMII0-CRS-DV/SPI1-CS1/PH-EINT2) ; off-sheet RGMII0-RXCTL
RGMII0-RXD0: U1.86(PH1/TWI0-SDA/I2S2-DOUT3/I2S2-DIN3/RGMII0-RXD0/RMII0-RXD0/TWI3-SDA/SPI1-WP/PH-EINT1) ; off-sheet RGMII0-RXD0
RGMII0-RXD1: U1.87(PH0/TWI0-SCK/I2S2-DOUT2/I2S2-DIN2/RGMII0-RXD1/RMII0-RXD1/TWI3-SCK/SPI1-HOLD/PH-EINT0) ; off-sheet RGMII0-RXD1
RGMII0-RXD2: U1.88(PH11/DMIC-DATA2/SPI2-MISO/RGMII0-RXD2/RMII0-NULL/PH-EINT11) ; off-sheet RGMII0-RXD2
RGMII0-RXD3: U1.89(PH10/DMIC-DATA1/SPI2-MOSI/RGMII0-RXD3/RMII0-NULL/PH-EINT10) ; off-sheet RGMII0-RXD3
RGMII0-TXCK: U1.90(PH6/UART3-RTS/I2S2-DOUT1/I2S2-DIN0/RGMII0-TXCK/RMII0-TXCK/SPI1-CLK/PH-EINT6) ; off-sheet RGMII0-TXCK
RGMII0-TXCTL: U1.91(PH7/UART3-CTS/SPI2-CS2/DSI-TRIG-LCD-TE1/RGMII0-TXCTL/RMII0-TXEN/PH-EINT7) ; off-sheet RGMII0-TXCTL
RGMII0-TXD0: U1.92(PH5/UART3-RX/I2S2-DIN1/I2S2-DOUT0/RGMII0-TXD0/RMII0-TXD0/SPI1-MOSI/PH-EINT5) ; off-sheet RGMII0-TXD0
RGMII0-TXD1: U1.93(PH4/UART3-TX/SPI2-CS3/I2S2-LRCK/RGMII0-TXD1/RMII0-TXD1/SPI1-CS0/PH-EINT4) ; off-sheet RGMII0-TXD1
RGMII0-TXD2: U1.94(PH14/UART5-RX/RGMII0-TXD2/RMII0-NULL/TWI7-SCK/PH-EINT14) ; off-sheet RGMII0-TXD2
RGMII0-TXD3: U1.96(PH13/UART5-TX/RGMII0-TXD3/RMII0-NULL/TWI7-SDA/PH-EINT13) ; off-sheet RGMII0-TXD3
S-TWI0-CTP0-SCK: U1.178(PL8/S-TWI1-SCK/S-UART1-TX/S-TWI0-SCK/S-TWI2-SCK/S-PWM0-6/PL-EINT8) ; off-sheet S-TWI0-CTP0-SCK
S-TWI0-CTP0-SDA: U1.179(PL9/S-TWI1-SDA/S-UART1-RX/S-TWI0-SDA/S-TWI2-SDA/S-PWM0-7/PL-EINT9) ; off-sheet S-TWI0-CTP0-SDA
SDC0-CLK: U1.74(PF2/SDC0-CLK/UART0-TX/TRACE-CLK/PF-EINT2) ; off-sheet SDC0-CLK
SDC0-CMD: U1.75(PF1/SDC0-CMD/JTAG-DO/TRACE-DATA2/PF-EINT1) ; off-sheet SDC0-CMD
SDC0-D0: U1.73(PF3/SDC0-D0/JTAG-DI/TRACE-DATA0/UART5-CTS/TWI2-SDA/PF-EINT3) ; off-sheet SDC0-D0
SDC0-D1: U1.72(PF0/SDC0-D1/JTAG-MS/TRACE-DATA3/UART5-RTS/TWI2-SCK/PF-EINT0) ; off-sheet SDC0-D1
SDC0-D2: U1.77(PF5/SDC0-D2/JTAG-CK/TRACE-DATA1/UART5-TX/PF-EINT5) ; off-sheet SDC0-D2
SDC0-D3: U1.76(PF4/SDC0-D3/UART0-RX/UART5-RX/PF-EINT4) ; off-sheet SDC0-D3
SDC0-DET: U1.71(PF6/PF-EINT6) ; off-sheet SDC0-DET
TWI8-SCK: U1.115(PB9/UART0-TX/I2S0-DIN2/I2S0-DOUT2/PWM1-1/WATCHDOG-SIG/LCD0-D16/TWI8-SCK/TWI0-SCK/PB-EINT9) U1.116(PB10/UART0-RX/I2S0-DIN3/I2S0-DOUT3/PWM1-2/PLL-LOCK-DBG/LCD0-D17/TWI8-SDA/TWI0-SDA/PB-EINT10) ; off-sheet TWI8-SDA, off-sheet TWI8-SCK  [also labelled TWI8-SDA]  [project net AUDIO-SCK]
UART0-RX: U1.107(PB1/UART2-RX/UART0-RX/SPI2-CLK/LCD0-D1/JTAG-CK/PB-EINT1) ; off-sheet UART0-RX
UART0-TX: U1.106(PB0/UART2-TX/UART0-TX/SPI2-CS0/DSI-TRIG-LCD-TE1/LCD0-D0/JTAG-MS/PB-EINT0) ; off-sheet UART0-TX
UART2-RX: U1.105(PJ27/PWM1-9/UART4-CTS/UART2-RX/DSI-TRIG-LCD-TE1/TWI5-SDA/SPI3-CS0/LCD0-D17/PJ-EINT27) ; off-sheet UART2-RX
UART2-TX: U1.104(PJ26/PWM1-8/UART4-RTS/UART2-TX/TWI5-SCK/SPI3-MISO/LCD0-D16/PJ-EINT26) ; off-sheet UART2-TX
UART3-RX: U1.101(PJ23/PWM1-5/UART3-RX/UART2-CTS/TWI7-SDA/TWI3-SDA/TWI11-SDA/LCD0-D9/PJ-EINT23) ; off-sheet UART3-RX
UART3-TX: U1.100(PJ22/PWM1-4/UART3-TX/UART2-RTS/TWI7-SCK/TWI3-SCK/TWI11-SCK/LCD0-D8/PJ-EINT22) ; off-sheet UART3-TX
UART4-RX: U1.103(PJ25/PWM1-7/UART4-RX/TWI4-SDA/SPI3-MOSI/PJ-EINT25) ; off-sheet UART4-RX
UART4-TX: U1.102(PJ24/PWM1-6/UART4-TX/TWI4-SCK/SPI3-CLK/PJ-EINT24) ; off-sheet UART4-TX
USB0-DM: U1.117(USB0-DM) ; off-sheet USB0-DM
USB0-DP: U1.118(USB0-DP) ; off-sheet USB0-DP
USB1-DM: U1.119(USB1-DM) ; off-sheet USB1-DM
USB1-DP: U1.120(USB1-DP) ; off-sheet USB1-DP
USB2-DM: U1.123(USB2-DM) ; off-sheet USB2-DM
USB2-DP: U1.124(USB2-DP) ; off-sheet USB2-DP
VBUS-EN: U1.172(PL2/S-UART1-TX/S-UART0-TX/S-TWI1-SDA/S-PWM0-0/PL-EINT2) ; off-sheet VBUS-EN

Not connected (* = marked no-connect by the designer): FID1 1(TP); FID2 1(TP); FID3 1(TP); FID4 1(TP); H1 1(TP); H2 1(TP); H3 1(TP); H4 1(TP); TP1 1(TP); TP2 1(TP); U1 1(PK14/MCSIB-CKN/PCIE-PERSTN/PWM0-7/NCSI1-D5/PK-EINT14) 2(PK15/MCSIB-CKP/PWM0-8/NCSI1-D4/PK-EINT15) 5(PK18/MCSIB-D3N/MCSI1-MCLK/UART2-RTS/PWM1-1/NCSI1-D1/TWI9-SCK/PK-EINT18) 141(TYPEC-RX2P/U3-RX0P/DP/EDP-TX2P) 142(TYPEC-RX2N/U3-RX0N/DP/EDP-TX2N) 143(TYPEC-TX2P/U3-TX0P/DP/EDP-TX3P) 144(TYPEC-TX2N/U3-TX0N/DP/EDP-TX3N) 146(PC7/NAND-RB1/SPI0-CS1/SPIF0-DQS/PC-EINT7) 151(PC15/NAND-DQ1/SDC2-D2/SDC3-D2/SPI0-WP/SPIF0-WP/PC-EINT15) 152(PC16/NAND-DQ0/SDC2-D7/SDC3-D7/SPI0-HOLD/SPIF0-HOLD/PC-EINT16) 153(PC13/NAND-DQ3/SDC2-D1/SDC3-D1/PC-EINT13) 154(PC14/NAND-DQ2/SDC2-D6/SDC3-D6/PC-EINT14) 159(PMU-IRQ) 160(PMU-SCK) 161(PMU-SDA) 176(PL6/S-JTAG-DO/S-UART0-TX/S-SPI0-MOSI/S-IR-RX/S-PWM0-4/PL-EINT6)

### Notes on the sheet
- 注意：
  专用接口-PMU-IRQ/PMU-SCK/PMU-SDA，禁止使用
  Note:
  Special interface - PMU-IRQ/PMU-SCK/PMU-SDA, do not use
- 1.if not used USB3.0&PCIE2.1 COMB0/1-CLKP/N
  tie to GND,power&signal pin can floating
  2.if used USB3.0,COMB0/1-CLKP/N tie to GND,PCIE-TEST tie to test port.
  3.if used PCIE2.1,PCIE-TEST tie to test port.
- 3.3V  PB PH PJ PL PD
- 1.8V  PM PK PE PC
- 注意：
  核心板供电电流需要1.5A@5V以上。
  Note:
  The power supply current of the core board
  needs more than 1.5A@5V
- NOTE:Combo0 100nF Cap placement
  need to close SOC：
  C139/C140/C141/C142
- 注意：
  LVDS和MIPI信号定义不一样，
  MIPI屏连接DSI这类名称信号线。
  Note:
  The definitions of LVDS and
  MIPI signals are different.
  The MIPI screen is connected
  to signal lines such as DSI..

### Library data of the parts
FID1-FID5 = T POINT R_2: FIDUCAL MARK; COMPONENT_WEIGHT: 30
H1-H4 = T POINT R_1: HOLE
R3 = R_Dup6
TP1 TP2 = T POINT R_1
U1 = AO4409_5

## Sheet 00 Change log.SchDoc
size 246 x 182 mm
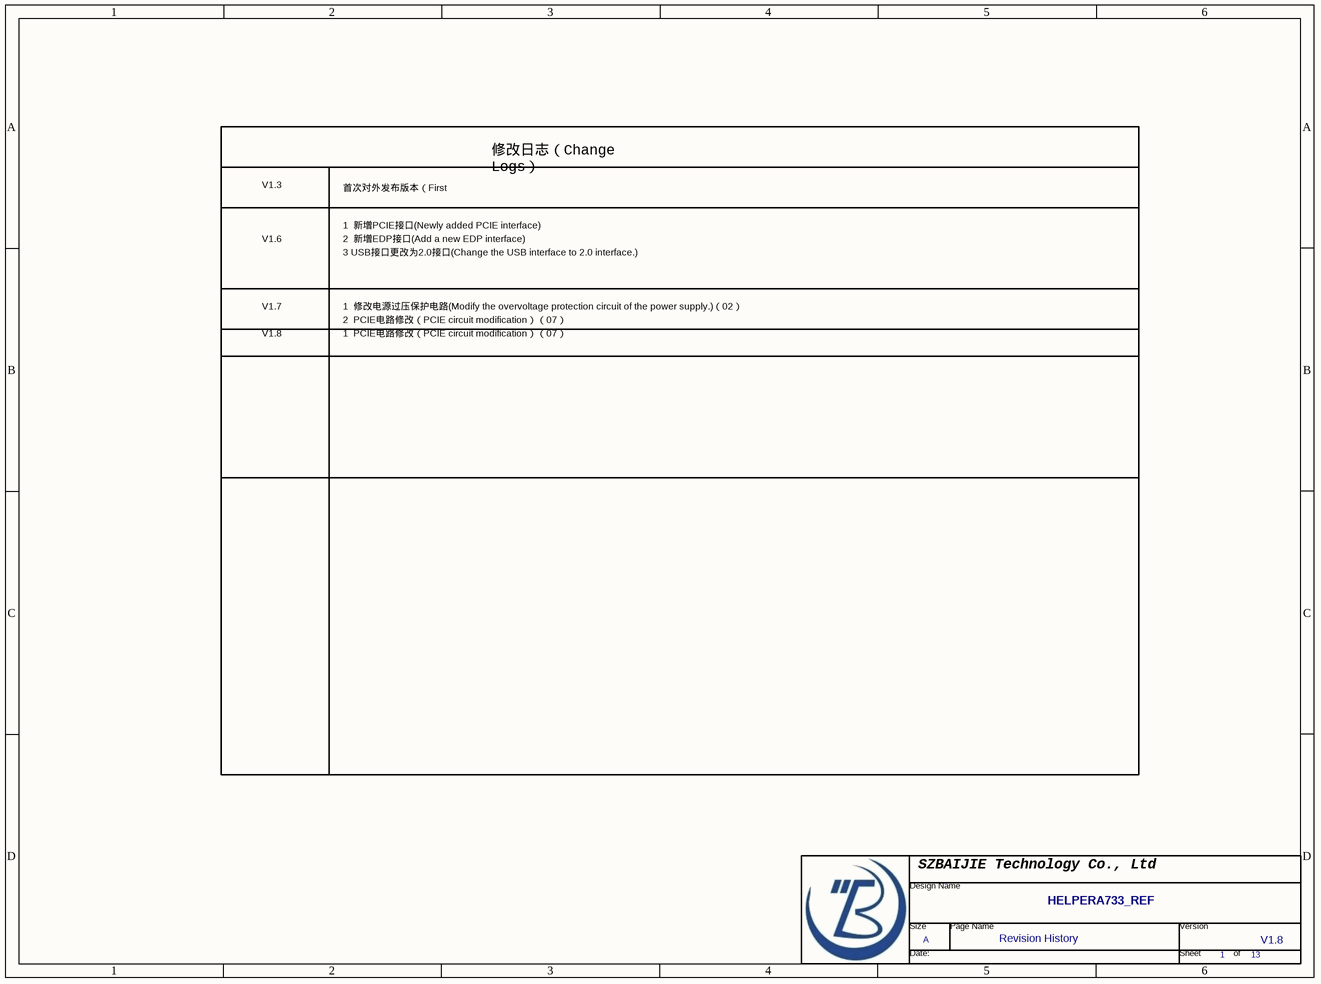
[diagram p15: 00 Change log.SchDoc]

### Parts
(Parts that share a designator on the sheet are numbered #1, #2 ... from top to bottom, then left to right.)
*#13  Page Count: 13  Page Number: 1  Page Size: A  Title: HELPERA733_REF  RevCode: V1.8  Doc: Revision History  (hidden comment: TitleBlock0-BJ)  (graphical)

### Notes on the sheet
- V1.3
- 首次对外发布版本（First
  release）
- 修改日志（Change
  Logs）
- V1.6
- 1  新增PCIE接口(Newly added PCIE interface)
- 2  新增EDP接口(Add a new EDP interface)
- 3 USB接口更改为2.0接口(Change the USB interface to 2.0 interface.)
- V1.7
- 1  修改电源过压保护电路(Modify the overvoltage protection circuit of the power supply.)（02）
- 2  PCIE电路修改（PCIE circuit modification）（07）
- V1.8
- 1  PCIE电路修改（PCIE circuit modification）（07）

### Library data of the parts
*#13 = TitleBlock0-BJ: OrgName: szBaijie

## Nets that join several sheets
5V: 12 HDMI (D69.1), 11 OTG_host_HUB (CU1.2 U13.5), 09 IO_ADC_BEEP (J16.1), 08  UART_485 (5 pins), 06 AUDIO AC101_AC101B (FB1.2), 04 LCD (8 pins), 02 Power (8 pins), 01 CORE (R3.1)
AFVCC-CSI: 03 CAMERA (CON1.36 CP1.1 D9.2), 01 CORE (U1.34)
AVCC: 09 IO_ADC_BEEP (D58.4 D58.7 J16.11), 06 AUDIO AC101_AC101B (R61.1), 01 CORE (U1.182)
AVDD-CSI: 03 CAMERA (5 pins), 01 CORE (U1.36)
DCIN: 04 LCD (CON2.26 CON2.27 CON2.28 CON2.29), 02 Power (13 pins)
DVDD-CSI: 03 CAMERA (CON1.37 CP2.1 D10.2), 01 CORE (U1.35)
GND: 12 HDMI (17 pins), 11 OTG_host_HUB (47 pins), 10 Ethernet (25 pins), 09 IO_ADC_BEEP (11 pins), 08  UART_485 (5 pins), 07 M (49 pins), 06 AUDIO AC101_AC101B (43 pins), 05 TF_KEY_RTC (25 pins), 04 LCD (92 pins), 03 CAMERA (33 pins), 02 Power (43 pins), 01 CORE (9 pins)
IOVDD-CSI: 03 CAMERA (CON1.39 CP4.1 D12.2), 01 CORE (U1.37)
PCIE-3V3: 07 M (19 pins), 04 LCD (5 pins), 02 Power (11 pins)
RTC-IN: 05 TF_KEY_RTC (D37.2 J8.2), 01 CORE (U1.166)
VCC-1V8: 07 M (6 pins), 06 AUDIO AC101_AC101B (RA20.1), 05 TF_KEY_RTC (R54.1), 04 LCD (R48.1 R49.1 R50.1), 02 Power (C20.2 U5.2)
VCC-3V3: 12 HDMI (D70.1 Q3.1 R87.2), 11 OTG_host_HUB (C84.1 C87.1 U42.9), 10 Ethernet (FB2.1), 09 IO_ADC_BEEP (D56.2 J16.3 J17.1), 08  UART_485 (9 pins), 06 AUDIO AC101_AC101B (RA16.1 RA22.2 RA23.2 RA24.1), 05 TF_KEY_RTC (5 pins), 04 LCD (10 pins), 02 Power (R119.1)
VCC_4G: 07 M (7 pins), 02 Power (10 pins)
4G-EN: 02 Power (R118.1 U43.4), 01 CORE (U1.173)
AP-RESET: 05 TF_KEY_RTC (D40.2 K3.2), 01 CORE (U1.167)
AUDIO-BCLK: 06 AUDIO AC101_AC101B (UA1.29), 01 CORE (U1.111)
AUDIO-DIN: 06 AUDIO AC101_AC101B (UA1.27), 01 CORE (U1.114)
AUDIO-DOUT: 06 AUDIO AC101_AC101B (UA1.26), 01 CORE (U1.113)
AUDIO-LRCK: 06 AUDIO AC101_AC101B (UA1.28), 01 CORE (U1.112)
AUDIO-MCLK: 06 AUDIO AC101_AC101B (UA1.30), 01 CORE (U1.110)
AUDIO-SCK: 06 AUDIO AC101_AC101B (RA22.1 RA23.1 UA1.31 UA1.32), 01 CORE (U1.115 U1.116)
CODEC-IRQ: 06 AUDIO AC101_AC101B (RA24.2 UA1.24), 01 CORE (U1.108)
CODEC-RST: 06 AUDIO AC101_AC101B (RA19.2), 01 CORE (U1.109)
CTP0-INT: 04 LCD (5 pins), 01 CORE (U1.180)
CTP0-RST: 04 LCD (D20.4 D20.7 J3.4 J5.1), 01 CORE (U1.181)
DSI0-CKN: 04 LCD (D81.1 J3.14 J4.14), 01 CORE (U1.56)
DSI0-CKP: 04 LCD (D80.1 J3.13 J4.15), 01 CORE (U1.55)
DSI0-DN0: 04 LCD (D13.2 D13.9 J3.10 J4.8), 01 CORE (U1.52)
DSI0-DN1: 04 LCD (D13.5 D13.6 J3.12 J4.11), 01 CORE (U1.54)
DSI0-DN2: 04 LCD (D21.1 D21.10 J3.34 J4.17), 01 CORE (U1.58)
DSI0-DN3: 04 LCD (D21.4 D21.7 J3.36 J4.20), 01 CORE (U1.60)
DSI0-DP0: 04 LCD (D13.1 D13.10 J3.9 J4.9), 01 CORE (U1.51)
DSI0-DP1: 04 LCD (D13.4 D13.7 J3.11 J4.12), 01 CORE (U1.53)
DSI0-DP2: 04 LCD (D21.2 D21.9 J3.33 J4.18), 01 CORE (U1.57)
DSI0-DP3: 04 LCD (D21.5 D21.6 J3.35 J4.21), 01 CORE (U1.59)
DSI1-CKN: 04 LCD (D16.5 D16.6 J3.22), 01 CORE (U1.66)
DSI1-CKP: 04 LCD (D16.4 D16.7 J3.21), 01 CORE (U1.65)
DSI1-DN0: 04 LCD (D83.1 J3.18), 01 CORE (U1.62)
DSI1-DN1: 04 LCD (D16.2 D16.9 J3.20), 01 CORE (U1.64)
DSI1-DN2: 04 LCD (D19.2 D19.9 J3.26), 01 CORE (U1.68)
DSI1-DN3: 04 LCD (D19.5 D19.6 J3.28), 01 CORE (U1.70)
DSI1-DP0: 04 LCD (D82.1 J3.17), 01 CORE (U1.61)
DSI1-DP1: 04 LCD (D16.1 D16.10 J3.19), 01 CORE (U1.63)
DSI1-DP2: 04 LCD (D19.1 D19.10 J3.25), 01 CORE (U1.67)
DSI1-DP3: 04 LCD (D19.4 D19.7 J3.27), 01 CORE (U1.69)
EDP-AUXN: 04 LCD (C28.1), 01 CORE (U1.135)
EDP-AUXP: 04 LCD (C25.1), 01 CORE (U1.136)
EDP-BL-PWMI: 04 LCD (RL1.1), 01 CORE (U1.175)
EDP-EN: 04 LCD (D17.2 R22.1), 01 CORE (U1.174)
EDP-HPD: 04 LCD (D15.2 R19.1 R20.2 R21.1), 01 CORE (U1.134)
EDP-TX0N: 04 LCD (C23.1), 01 CORE (U1.138)
EDP-TX0P: 04 LCD (C24.1), 01 CORE (U1.137)
EDP-TX1N: 04 LCD (C21.1), 01 CORE (U1.140)
EDP-TX1P: 04 LCD (C22.1), 01 CORE (U1.139)
FEL: 05 TF_KEY_RTC (D39.1 K1.1), 01 CORE (U1.145)
GPADC4: 09 IO_ADC_BEEP (D59.2 D59.9 J16.14), 01 CORE (U1.155)
GPADC5: 09 IO_ADC_BEEP (D59.1 D59.10 J16.13), 01 CORE (U1.156)
GPADC6: 09 IO_ADC_BEEP (D58.5 D58.6 J16.12), 01 CORE (U1.157)
HCEC: 12 HDMI (Q3.2 R87.1), 01 CORE (U1.39)
HHPD: 12 HDMI (R89.1 R92.1), 01 CORE (U1.40)
HP-DET-PE11: 06 AUDIO AC101_AC101B (RA9.2), 01 CORE (U1.129)
HSCL: 12 HDMI (R90.1 U14.15 U16.2 U16.9), 01 CORE (U1.42)
HSDA: 12 HDMI (R91.1 U14.16 U16.4 U16.7), 01 CORE (U1.41)
HTX0N: 12 HDMI (U14.9 U15.2 U15.9), 01 CORE (U1.45)
HTX0P: 12 HDMI (U14.7 U15.1 U15.10), 01 CORE (U1.46)
HTX1N: 12 HDMI (DE1.5 DE1.6 U14.6), 01 CORE (U1.47)
HTX1P: 12 HDMI (DE1.4 DE1.7 U14.4), 01 CORE (U1.48)
HTX2N: 12 HDMI (DE1.2 DE1.9 U14.3), 01 CORE (U1.49)
HTX2P: 12 HDMI (DE1.1 DE1.10 U14.1), 01 CORE (U1.50)
HTXCN: 12 HDMI (U14.12 U15.5 U15.6), 01 CORE (U1.43)
HTXCP: 12 HDMI (U14.10 U15.4 U15.7), 01 CORE (U1.44)
IO-RESET: 05 TF_KEY_RTC (D42.1 K4.1 R54.2), 01 CORE (U1.6)
LCD0-EN: 04 LCD (D22.1 J3.40 R41.2 U6.4), 01 CORE (U1.81)
LCD0-HSYNC: 04 LCD (D25.1 J3.29), 01 CORE (U1.78)
LCD0-PWM: 04 LCD (D23.1 J3.39 R43.1 U7.4), 01 CORE (U1.80)
LCD0-VSYNC: 04 LCD (D24.1 J3.30), 01 CORE (U1.79)
LCD-PE3: 04 LCD (J6.3 R50.2), 01 CORE (U1.7)
LCD-PE4: 04 LCD (J6.2 R49.2), 01 CORE (U1.8)
LCD-PE5: 04 LCD (J6.1 R48.2), 01 CORE (U1.9)
LCD-RST: 04 LCD (C33.2 D28.1 J4.5 R31.2), 01 CORE (U1.177)
LRADC0: 05 TF_KEY_RTC (D43.2 J9.1), 01 CORE (U1.183)
MCSI0-MCLK: 03 CAMERA (CON1.26 D7.1 D7.10), 01 CORE (U1.26)
MCSI2-MCLK: 03 CAMERA (CON1.28 D7.2 D7.9), 01 CORE (U1.27)
MCSI-RST-F: 03 CAMERA (CON1.31 D7.5 D7.6), 01 CORE (U1.29)
MCSI-RST-R: 03 CAMERA (CON1.32 D8.4 D8.7), 01 CORE (U1.31)
MCSI-SCK-TWI2: 03 CAMERA (CON1.34 D8.2 D8.9 R15.2), 01 CORE (U1.32)
MCSI-SDA-TWI2: 03 CAMERA (CON1.35 D8.1 D8.10 R16.2), 01 CORE (U1.33)
MCSI-STBY-F: 03 CAMERA (CON1.30 D7.4 D7.7), 01 CORE (U1.28)
MCSI-STBY-R: 03 CAMERA (CON1.33 D8.5 D8.6), 01 CORE (U1.30)
MCSIA-CKN: 03 CAMERA (CON1.14 D5.1 D5.10), 01 CORE (U1.18)
MCSIA-CKP: 03 CAMERA (CON1.15 D5.2 D5.9), 01 CORE (U1.19)
MCSIA-D0N: 03 CAMERA (CON1.11 D3.4 D3.7), 01 CORE (U1.16)
MCSIA-D0P: 03 CAMERA (CON1.12 D3.5 D3.6), 01 CORE (U1.17)
MCSIA-D1N: 03 CAMERA (CON1.8 D3.1 D3.10), 01 CORE (U1.14)
MCSIA-D1P: 03 CAMERA (CON1.9 D3.2 D3.9), 01 CORE (U1.15)
MCSIA-D2N: 03 CAMERA (CON1.5 D4.4 D4.7), 01 CORE (U1.12)
MCSIA-D2P: 03 CAMERA (CON1.6 D4.5 D4.6), 01 CORE (U1.13)
MCSIA-D3N: 03 CAMERA (CON1.2 D4.1 D4.10), 01 CORE (U1.10)
MCSIA-D3P: 03 CAMERA (CON1.3 D4.2 D4.9), 01 CORE (U1.11)
MCSIC-CKN: 03 CAMERA (CON1.23 D6.4 D6.7), 01 CORE (U1.24)
MCSIC-CKP: 03 CAMERA (CON1.24 D6.5 D6.6), 01 CORE (U1.25)
MCSIC-D0N: 03 CAMERA (CON1.20 D6.1 D6.10), 01 CORE (U1.22)
MCSIC-D0P: 03 CAMERA (CON1.21 D6.2 D6.9), 01 CORE (U1.23)
MCSIC-D1N: 03 CAMERA (CON1.17 D5.4 D5.7), 01 CORE (U1.20)
MCSIC-D1P: 03 CAMERA (CON1.18 D5.5 D5.6), 01 CORE (U1.21)
MDC: 10 Ethernet (U10.13), 01 CORE (U1.98)
MDIO: 10 Ethernet (RE3.2 U10.14), 01 CORE (U1.97)
PA-SHDN-PE15: 06 AUDIO AC101_AC101B (R55.2 U8.1), 01 CORE (U1.133)
PC2: 09 IO_ADC_BEEP (D60.2 D60.9 J16.18), 01 CORE (U1.149)
PC3: 09 IO_ADC_BEEP (D60.5 D60.6 J16.20), 01 CORE (U1.147)
PC4: 09 IO_ADC_BEEP (D60.4 D60.7 J16.19), 01 CORE (U1.148)
PC12: 09 IO_ADC_BEEP (D60.1 D60.10 J16.17), 01 CORE (U1.150)
PCIE1-REFCLKN: 07 M (CB11.1), 01 CORE (U1.128)
PCIE1-REFCLKP: 07 M (CB10.1), 01 CORE (U1.127)
PCIE1-RXN: 07 M (R243.1), 01 CORE (U1.126)
PCIE1-RXP: 07 M (R242.1), 01 CORE (U1.125)
PCIE1-TXN: 07 M (CB5.1), 01 CORE (U1.122)
PCIE1-TXP: 07 M (CB4.1), 01 CORE (U1.121)
PCIE-CLKREQN: 07 M (Q10.2 R229.2), 01 CORE (U1.131)
PCIE-PERSTN: 07 M (Q11.2 R231.2), 01 CORE (U1.130)
PCIE-WAKEN: 07 M (Q9.2 R120.2), 01 CORE (U1.132)
PHYRSTB: 10 Ethernet (CE7.2 RE2.2 U10.12), 01 CORE (U1.99)
PK10: 09 IO_ADC_BEEP (D57.5 D57.6 J16.8), 01 CORE (U1.186)
PK11: 09 IO_ADC_BEEP (D57.4 D57.7 J16.7), 01 CORE (U1.187)
PK12: 09 IO_ADC_BEEP (D58.2 D58.9 J16.10), 01 CORE (U1.184)
PK13: 09 IO_ADC_BEEP (D58.1 D58.10 J16.9), 01 CORE (U1.185)
PK16: 09 IO_ADC_BEEP (D57.2 D57.9 J16.6), 01 CORE (U1.3)
PK17: 09 IO_ADC_BEEP (D57.1 D57.10 J16.5), 01 CORE (U1.4)
PL12: 09 IO_ADC_BEEP (D59.5 D59.6 J16.16), 01 CORE (U1.171)
PL13: 09 IO_ADC_BEEP (D59.4 D59.7 J16.15), 01 CORE (U1.170)
PM5-BEEP: 09 IO_ADC_BEEP (R81.1), 01 CORE (U1.169)
PWRON: 05 TF_KEY_RTC (C46.1 D41.2 K2.2), 01 CORE (U1.168)
RGMII0-CLK-25M: 10 Ethernet (R86.1), 01 CORE (U1.82)
RGMII0-RXCK: 10 Ethernet (RE10.1), 01 CORE (U1.84)
RGMII0-RXCTL: 10 Ethernet (RE11.1), 01 CORE (U1.85)
RGMII0-RXD0: 10 Ethernet (RE9.1 U10.25), 01 CORE (U1.86)
RGMII0-RXD1: 10 Ethernet (RE8.1 U10.24), 01 CORE (U1.87)
RGMII0-RXD2: 10 Ethernet (RE5.1 U10.23), 01 CORE (U1.88)
RGMII0-RXD3: 10 Ethernet (RE13.1 U10.22), 01 CORE (U1.89)
RGMII0-TXCK: 10 Ethernet (RE7.1), 01 CORE (U1.90)
RGMII0-TXCTL: 10 Ethernet (RE6.1), 01 CORE (U1.91)
RGMII0-TXD0: 10 Ethernet (U10.18), 01 CORE (U1.92)
RGMII0-TXD1: 10 Ethernet (U10.17), 01 CORE (U1.93)
RGMII0-TXD2: 10 Ethernet (U10.16), 01 CORE (U1.94)
RGMII0-TXD3: 10 Ethernet (U10.15), 01 CORE (U1.96)
RGMII-CLKIN-125M: 10 Ethernet (RE12.1), 01 CORE (U1.83)
S-TWI0-CTP0-SCK: 04 LCD (5 pins), 01 CORE (U1.178)
S-TWI0-CTP0-SDA: 04 LCD (5 pins), 01 CORE (U1.179)
SDC0-CLK: 05 TF_KEY_RTC (D38.1 D38.10 J7.5), 01 CORE (U1.74)
SDC0-CMD: 05 TF_KEY_RTC (D35.2 J7.3 R52.2), 01 CORE (U1.75)
SDC0-D0: 05 TF_KEY_RTC (D38.2 D38.9 J7.7), 01 CORE (U1.73)
SDC0-D1: 05 TF_KEY_RTC (D38.4 D38.7 J7.8), 01 CORE (U1.72)
SDC0-D2: 05 TF_KEY_RTC (D33.2 J7.1), 01 CORE (U1.77)
SDC0-D3: 05 TF_KEY_RTC (D34.2 J7.2), 01 CORE (U1.76)
SDC0-DET: 05 TF_KEY_RTC (D38.5 D38.6 R53.1), 01 CORE (U1.71)
UART0-RX: 11 OTG_host_HUB (U12.8), 01 CORE (U1.107)
UART0-TX: 11 OTG_host_HUB (U12.9), 01 CORE (U1.106)
UART2-RX: 08  UART_485 (D51.1 R69.1), 01 CORE (U1.105)
UART2-TX: 08  UART_485 (R74.2 U9.4), 01 CORE (U1.104)
UART3-RX: 08  UART_485 (D55.2 D55.9 J14.3 R77.2), 01 CORE (U1.101)
UART3-TX: 08  UART_485 (D55.1 D55.10 J14.2 R78.2), 01 CORE (U1.100)
UART4-RX: 08  UART_485 (D55.4 D55.7 J15.3 R79.2), 01 CORE (U1.103)
UART4-TX: 08  UART_485 (D55.5 D55.6 J15.2 R80.2), 01 CORE (U1.102)
USB0-DM: 11 OTG_host_HUB (U11.1), 01 CORE (U1.117)
USB0-DP: 11 OTG_host_HUB (U11.2), 01 CORE (U1.118)
USB1-DM: 11 OTG_host_HUB (U42.5), 01 CORE (U1.119)
USB1-DP: 11 OTG_host_HUB (U42.6), 01 CORE (U1.120)
USB2-DM: 07 M (CON3.36), 01 CORE (U1.123)
USB2-DP: 07 M (CON3.38), 01 CORE (U1.124)
VBUS-EN: 11 OTG_host_HUB (RU1.2 U13.4), 01 CORE (U1.172)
